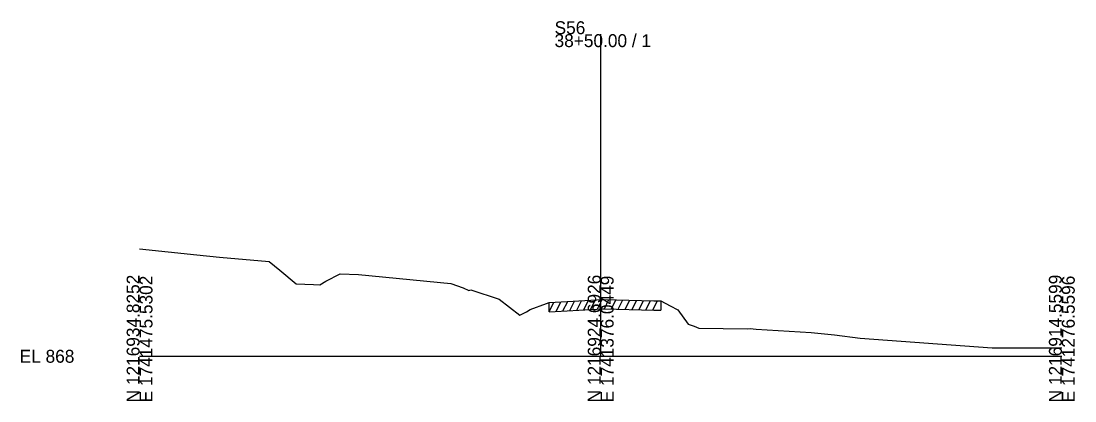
# Model space of a CAD drawing. Extents: x -26 to 1203, y -10 to 19541.
# Drawn here: x -25.7 to 202.8, y 13490.3 to 13572.7 of the extents above; entities that cross this region are included whole.
import ezdxf

# ---------------------------------------------------------------- set-up
doc = ezdxf.new("R2010")
doc.units = 0
for name, color, linetype in [('RD_GPK_XS_Cell', 7, 'Continuous'), ('RD_XS_ExGround', 7, 'Continuous'), ('RD_XS_ExPaveRet', 7, 'Continuous'), ('RD_XS_TX_Elev_EX', 7, 'Continuous')]:
    doc.layers.add(name, color=color, linetype=linetype)

msp = doc.modelspace()

# ---------------------------------------------------------------- linework, layer by layer
at = {"layer": 'RD_GPK_XS_Cell'}
for p, q in [((100, 13500), (100, 13569.89)), ((0, 13500), (100, 13500)), ((100, 13500), (200, 13500))]:
    msp.add_line(p, q, dxfattribs=at)
at = {"layer": 'RD_XS_ExGround'}
msp.add_lwpolyline([(0, 13523.3), (12.44, 13521.98), (17.37, 13521.53), (28.11, 13520.54), (30.41, 13518.68), (33.95, 13515.69), (37.73, 13515.59), (39.09, 13515.53), (40.36, 13516.3), (43.51, 13517.91), (47.49, 13517.76), (67.49, 13515.77), (70.16, 13514.85), (71.39, 13514.27), (71.86, 13514.45), (77.96, 13512.42), (82.44, 13508.94), (83.91, 13509.66), (84.73, 13510.16), (88.28, 13511.46), (88.81, 13511.66), (99.16, 13512.25), (100, 13512.29), (100.72, 13512.32), (111.51, 13512.03), (113.07, 13512.01), (115.09, 13510.95), (116.7, 13510.1), (118.99, 13506.96), (120.25, 13506.51), (121.29, 13506.07), (131.87, 13505.95), (132.38, 13506.05), (133.73, 13505.88), (145.63, 13505.14), (150.72, 13504.66), (156.29, 13503.96), (184.87, 13501.8), (200, 13501.8)], dxfattribs=at)
at = {"layer": 'RD_XS_ExPaveRet'}
for p, q in [((88.81, 13509.66), (89.84, 13511.72)), ((88.81, 13509.66), (88.81, 13511.66)), ((90.31, 13509.75), (91.34, 13511.81)), ((91.81, 13509.83), (92.84, 13511.89)), ((93.31, 13509.92), (94.34, 13511.98)), ((94.81, 13510), (95.84, 13512.06)), ((96.31, 13510.09), (97.34, 13512.15)), ((97.81, 13510.17), (98.84, 13512.23)), ((99.31, 13510.26), (100.33, 13512.31)), ((100.81, 13510.32), (101.8, 13512.29)), ((102.31, 13510.28), (103.3, 13512.25)), ((103.81, 13510.24), (104.8, 13512.21)), ((105.31, 13510.2), (106.3, 13512.17)), ((106.81, 13510.16), (107.8, 13512.13)), ((108.31, 13510.12), (109.3, 13512.09)), ((109.81, 13510.08), (110.8, 13512.05)), ((111.31, 13510.04), (112.3, 13512.02)), ((113.07, 13512.01), (113.07, 13510.01)), ((88.81, 13509.66), (99.16, 13510.25)), ((99.16, 13510.25), (100, 13510.29)), ((100, 13510.29), (100.72, 13510.32)), ((100.72, 13510.32), (111.51, 13510.03)), ((111.51, 13510.03), (113.07, 13510.01))]:
    msp.add_line(p, q, dxfattribs=at)

# ---------------------------------------------------------------- texts
at = {"layer": 'RD_GPK_XS_Cell'}
for s, p in [('S56', (90, 13569.89)), ('38+50.00 / 1', (90, 13567.09)), ('EL 868', (-26, 13498.6))]:
    msp.add_text(s, height=2.8, dxfattribs=at).set_placement(p)
for s, p in [('N 1216934.8252', (0, 13490)), ('E 1741475.5302', (2.8, 13490)), ('N 1216924.6926', (100, 13490)), ('E 1741376.0449', (102.8, 13490)), ('N 1216914.5599', (200, 13490)), ('E 1741276.5596', (202.8, 13490))]:
    msp.add_text(s, height=2.8, rotation=90, dxfattribs=at).set_placement(p)
at = {"layer": 'RD_XS_TX_Elev_EX'}
msp.add_text('874.14', height=0.1, rotation=90, dxfattribs=at).set_placement((100.1, 13512.29))

doc.saveas('drawing.dxf')
